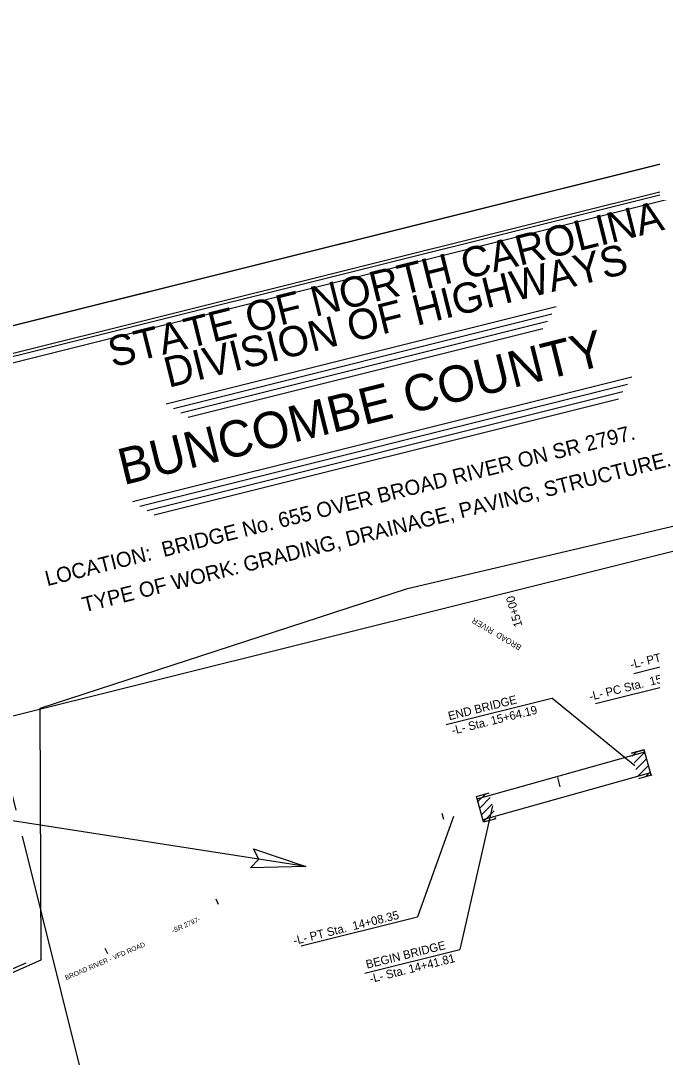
# Model space of a CAD drawing. Extents: x 1030323 to 1034123, y 654802 to 657751.
# Drawn here: x 1030952 to 1031475, y 656487 to 657344 of the extents above; entities that cross this region are included whole.
import ezdxf

# ---------------------------------------------------------------- set-up
doc = ezdxf.new("R2010")
doc.units = 0
for name, color, linetype in [('Default', 7, 'Continuous'), ('Old_Level_1', 7, 'Continuous'), ('Prop Approach Slab', 7, 'Continuous'), ('Prop Approach Slab Hatching', 7, 'Continuous'), ('Prop EOT', 7, 'Continuous'), ('Prop Horizontal Alignment Station Label', 7, 'Continuous'), ('Prop Horizontal Alignment Tick Label', 7, 'Continuous'), ('Prop Horizontal Alignment Tick Large', 7, 'Continuous'), ('Prop Horizontal Alignment Tick Small', 7, 'Continuous'), ('Prop Paved Shoulder', 7, 'Continuous'), ('Prop Terminator CELL', 7, 'Continuous'), ('Sheet Clip Boundary CELL', 7, 'Continuous'), ('Sheet Cutting Line CELL', 7, 'Continuous'), ('Sheet Data Field CELL', 7, 'Continuous'), ('Sheet Plot Border Inside CELL', 7, 'Continuous'), ('Sheet Plot Border Outside CELL', 7, 'Continuous'), ('Sheet Title CELL', 7, 'Continuous'), ('Sheet Title Data Points CELL', 7, 'Continuous')]:
    doc.layers.add(name, color=color, linetype=linetype)

msp = doc.modelspace()

# ---------------------------------------------------------------- linework, layer by layer
at = {"layer": 'Old_Level_1'}
msp.add_line((1030956.64, 656564.48), (1030860.94, 656523.28), dxfattribs=at)
at = {"layer": 'Prop Approach Slab'}
for p, q in [((1031457.91, 656738.11), (1031468.32, 656741.01)), ((1031474.23, 656719.99), (1031468.37, 656741.02)), ((1031335.42, 656681.27), (1031329.55, 656702.31))]:
    msp.add_line(p, q, dxfattribs=at)
at = {"layer": 'Prop Approach Slab Hatching'}
for p, q in [((1031458.57, 656735.74), (1031462.11, 656739.28)), ((1031460.11, 656730.21), (1031468.93, 656739.02)), ((1031461.65, 656724.68), (1031470.47, 656733.49)), ((1031463.2, 656719.15), (1031472.01, 656727.96)), ((1031469.89, 656718.77), (1031473.55, 656722.43)), ((1031330.77, 656698.17), (1031336.99, 656704.38)), ((1031330.77, 656698.17), (1031336.99, 656704.38)), ((1031332.32, 656692.64), (1031341.09, 656701.42)), ((1031332.32, 656692.64), (1031341.09, 656701.42)), ((1031333.86, 656687.11), (1031342.63, 656695.89)), ((1031333.86, 656687.11), (1031342.63, 656695.89)), ((1031335.4, 656681.59), (1031344.18, 656690.36)), ((1031335.4, 656681.59), (1031344.18, 656690.36)), ((1031344.77, 656683.88), (1031345.72, 656684.83)), ((1031344.77, 656683.88), (1031345.72, 656684.83))]:
    msp.add_line(p, q, dxfattribs=at)
at = {"layer": 'Prop EOT'}
for p, q in [((1031330.13, 656700.48), (1031468.88, 656739.17)), ((1031473.72, 656721.84), (1031334.9, 656683.12))]:
    msp.add_line(p, q, dxfattribs=at)
at = {"layer": 'Prop Horizontal Alignment Station Label'}
for p, q in [((1031459.94, 656804.14), (1031560.6, 656829.24)), ((1031428.17, 656779.22), (1031523.94, 656803.09)), ((1031304.7, 656761.96), (1031392.1, 656783.76)), ((1031460.84, 656727.59), (1031392.1, 656783.76)), ((1031342.96, 656694.71), (1031315.76, 656575.91)), ((1031188.45, 656644.42), (1030925.24, 656685.27)), ((1031310.74, 656685.73), (1031280.77, 656602.75)), ((1031184.56, 656578.76), (1031280.77, 656602.75)), ((1031237.12, 656556.3), (1031315.76, 656575.91))]:
    msp.add_line(p, q, dxfattribs=at)
at = {"layer": 'Prop Horizontal Alignment Tick Large'}
msp.add_line((1031399.01, 656710.35), (1031396.86, 656718.05), dxfattribs=at)
at = {"layer": 'Prop Horizontal Alignment Tick Small'}
for p, q in [((1031302.7, 656683.45), (1031301.32, 656688.26)), ((1031116.1, 656612.91), (1031114.06, 656617.47)), ((1031024.45, 656572.18), (1031022.41, 656576.74))]:
    msp.add_line(p, q, dxfattribs=at)
at = {"layer": 'Prop Paved Shoulder'}
for p, q in [((1031468.32, 656741.01), (1031457.91, 656738.11)), ((1031468.32, 656741.01), (1031457.91, 656738.11)), ((1031474.23, 656719.99), (1031463.78, 656717.07)), ((1031474.23, 656719.99), (1031474.96, 656720.18)), ((1031329.55, 656702.31), (1031340.03, 656705.23)), ((1031335.42, 656681.27), (1031345.9, 656684.2))]:
    msp.add_line(p, q, dxfattribs=at)
at = {"layer": 'Prop Terminator CELL'}
msp.add_lwpolyline([(1031145.17, 656658.98), (1031188.45, 656644.42), (1031142.51, 656643.45), (1031149.42, 656650.48)], close=True, dxfattribs=at)
at = {"layer": 'Sheet Clip Boundary CELL'}
msp.add_lwpolyline([(1031088.75, 656293.37), (1030994.11, 656269.56), (1030843.5, 656511.74), (1030969.21, 656567.19), (1030968.58, 656775.34), (1031272.57, 656874.34), (1031522.82, 656933.1), (1031562.8, 656947.62), (1031759.53, 656972.55), (1031879.7, 656490.58)], close=True, dxfattribs=at)
at = {"layer": 'Sheet Cutting Line CELL'}
msp.add_line((1030322.99, 656936.36), (1031956.96, 657343.76), dxfattribs=at)
at = {"layer": 'Sheet Plot Border Inside CELL'}
msp.add_lwpolyline([(1030596.28, 655893.96), (1032213.28, 656297.13), (1031958.03, 657320.89), (1030341.03, 656917.72)], close=True, dxfattribs=at)
at = {"layer": 'Sheet Plot Border Outside CELL'}
msp.add_lwpolyline([(1031956.96, 657343.76), (1030322.99, 656936.36), (1030589.1, 655869.05), (1032223.08, 656276.44)], close=True, dxfattribs=at)
at = {"layer": 'Sheet Title CELL'}
for p, q in [((1031072.76, 657026.89), (1031395.62, 657107.4)), ((1031078.82, 657023.26), (1031391.98, 657101.33)), ((1031084.88, 657019.6), (1031388.34, 657095.28)), ((1031090.94, 657015.96), (1031384.7, 657089.21)), ((1031044.81, 656946.14), (1031458.16, 657049.19)), ((1031050.87, 656942.5), (1031454.52, 657043.13)), ((1031056.94, 656938.84), (1031450.87, 657037.08)), ((1031063, 656935.21), (1031447.24, 657031))]:
    msp.add_line(p, q, dxfattribs=at)
for points in [[(1031936.83, 657312.97), (1030500.76, 656954.93)], [(1031933.17, 657306.91), (1030555.36, 656963.38)], [(1030948.53, 656691.15), (1030930.1, 656765.11), (1031721.05, 656962.31), (1031730.37, 656924.93)], [(1031755.78, 656823), (1031841.22, 656480.34), (1031050.26, 656283.14), (1030953.9, 656669.65)]]:
    msp.add_lwpolyline(points, dxfattribs=at)
at = {"layer": 'Sheet Title Data Points CELL'}
for p, q in [((1031191.66, 657125.97), (1031191.66, 657125.97)), ((1031327.59, 657095.42), (1031327.59, 657095.42)), ((1031249.38, 657012.5), (1031249.38, 657012.5)), ((1031379.02, 656988.8), (1031379.02, 656988.8))]:
    msp.add_line(p, q, dxfattribs=at)

# ---------------------------------------------------------------- texts
at = {"layer": 'Default'}
msp.add_text('BROAD  RIVER', height=4.8, rotation=149.46622, dxfattribs=at).set_placement((1031367.33, 656827.06))
at = {"layer": 'Old_Level_1'}
for s, rotation, p in [('-SR 2797-', 23.96198, (1031078.41, 656589.27)), ('BROAD RIVER - VFD ROAD', 23.18138, (1030990.14, 656550.39))]:
    msp.add_text(s, height=4, rotation=rotation, dxfattribs=at).set_placement(p)
at = {"layer": 'Prop Horizontal Alignment Station Label'}
for s, rotation, p in [('-L- PT Sta.  16+47.62', 14, (1031457.8, 656807.84)), ('-L- PC Sta.  15+79.30', 14, (1031423.86, 656781.49)), ('END BRIDGE', 13.98333, (1031307.13, 656765.3)), ('-L- Sta. 15+64.19', 13.98333, (1031310.09, 656753.41)), ('-L- PT Sta.  14+08.35', 14, (1031178.99, 656579.59)), ('BEGIN BRIDGE', 13.98333, (1031239.05, 656559.93)), ('-L- Sta. 14+41.81', 13.98333, (1031242.01, 656548.05))]:
    msp.add_text(s, height=7, rotation=rotation, dxfattribs=at).set_placement(p)
at = {"layer": 'Prop Horizontal Alignment Tick Label'}
msp.add_text('15+00', height=7, rotation=105.58243, dxfattribs=at).set_placement((1031367.73, 656843.55))
at = {"layer": 'Sheet Data Field CELL'}
for s, height, p in [('BUNCOMBE COUNTY', 30, (1031037.48, 656959.67)), ('LOCATION:  BRIDGE No. 655 OVER BROAD RIVER ON SR 2797.', 12.5001, (1030974.36, 656876.21))]:
    msp.add_text(s, height=height, rotation=14, dxfattribs=at).set_placement(p)
at = {"layer": 'Sheet Title CELL'}
for s, height, p in [('STATE OF NORTH CAROLINA', 24.9999, (1031028.36, 657056.99)), ('DIVISION OF HIGHWAYS', 24.9999, (1031074.69, 657040.21)), ('TYPE OF WORK: GRADING, DRAINAGE, PAVING, STRUCTURE.', 12.5001, (1031005.07, 656854.51))]:
    msp.add_text(s, height=height, rotation=14, dxfattribs=at).set_placement(p)

doc.saveas('drawing.dxf')
